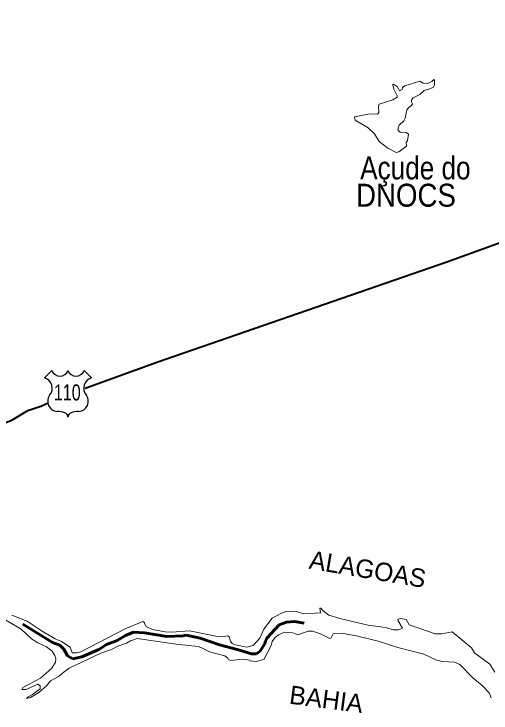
# Model space of a CAD drawing. Extents: x 553962 to 842807, y 8883888 to 9032388.
# Drawn here: x 591570 to 601949, y 8954910 to 8970115 of the extents above; entities that cross this region are included whole.
import ezdxf
from ezdxf.enums import TextEntityAlignment as Align

# ---------------------------------------------------------------- set-up
doc = ezdxf.new("R2010")
doc.units = 0
doc.header["$LTSCALE"] = 200
doc.linetypes.add('LONG_DASH_SHORT_DASH', pattern=[9.9, 6, -1.2, 1.5, -1.2])
for name, color, linetype, lineweight in [('12', 7, 'Continuous', 25), ('22', 7, 'Continuous', 13), ('25', 7, 'Continuous', 13), ('48', 7, 'Continuous', 25), ('7', 7, 'Continuous', 90), ('9', 7, 'Continuous', 90)]:
    doc.layers.add(name, color=color, linetype=linetype, lineweight=lineweight)
doc.layers.add('42', color=7, linetype='Continuous')
doc.layers.add('50', color=7, linetype='Continuous')

msp = doc.modelspace()

# ---------------------------------------------------------------- linework, layer by layer
at = {"layer": '12', "lineweight": 40}
for points in [[(593118.3, 8961975.5), (594700.8, 8962547.5), (600985.5, 8964722.4), (602091.6, 8965119.9), (602697.1, 8965318.9), (609861, 8967928.7)], [(587134, 8956453.8), (587843.6, 8957685.7), (587923.7, 8957988.5), (588169.9, 8958625.1), (588237, 8958904.7), (588304.1, 8959099.5), (588468, 8959448.9), (588578.9, 8959635.8), (588673.7, 8959750.1), (588777.5, 8959843.1), (589203.6, 8960089.7), (589393.4, 8960175.8), (589428.5, 8960178.5), (589560.1, 8960264.6), (589648.9, 8960297.2), (590059.4, 8960543.5), (591188.1, 8961101.4), (591408.7, 8961235.4), (591525.3, 8961280.9), (591868.7, 8961488.1), (592154.1, 8961587.2), (592311.1, 8961655)]]:
    msp.add_lwpolyline(points, dxfattribs=at)
at = {"layer": '22'}
for points in [[(599809.1, 8968571.9), (599807.2, 8968579.6), (599825.8, 8968589.3), (599913, 8968531.8), (599957.7, 8968446.1), (600016.8, 8968470.3), (600024, 8968513.4), (600074.7, 8968549.4), (600397.5, 8968653.6), (600470.2, 8968613.3), (600565, 8968605), (600658.8, 8968647.2), (600702.7, 8968690.5), (600704.6, 8968688.3)], [(600704.6, 8968688.3), (600721.8, 8968668.3), (600716.4, 8968577.4), (600697.2, 8968526.2), (600615.2, 8968484), (600495.5, 8968451.8), (600399.8, 8968360.6), (600257.6, 8968290.3), (600215.3, 8968243.9), (600215.2, 8968203.3), (600238.2, 8968158.5), (600215, 8968118.4), (600157.8, 8968080.1), (600117.6, 8968027.2), (600078.7, 8967845.6), (600049.3, 8967791.2), (599953.8, 8967693.5), (599926.3, 8967638.5), (599930.5, 8967583.1), (599969.1, 8967544.5), (600104.8, 8967540.5), (600151.1, 8967502.5), (600134.3, 8967366.4), (600104.7, 8967317.5), (600109.2, 8967237.7)], [(598979.7, 8967874.9), (598979.6, 8967875.5), (599301.7, 8967946.2), (599480.2, 8967933.8), (599509.8, 8967969.9), (599501.3, 8968101.1), (599516.3, 8968150.1), (599811.5, 8968247.9), (599904.8, 8968303.2), (599909, 8968337.3), (599832.8, 8968479.3), (599809.1, 8968571.9)], [(599516.6, 8967344.8), (599411.9, 8967506.8), (599276.3, 8967640.2), (598993.8, 8967806), (598979.7, 8967874.9)], [(600109.2, 8967237.7), (599943.1, 8967117.9), (599886.4, 8967105.1), (599701.2, 8967194.2), (599516.6, 8967344.8)]]:
    msp.add_lwpolyline(points, dxfattribs=at)
at = {"layer": '25'}
for points in [[(602034.6, 8955801.4), (601924, 8955971.4), (601588.5, 8956218.1), (601523.3, 8956327.4), (601101.6, 8956673.9), (600881.9, 8956635.9), (600732.9, 8956633.6), (600171.5, 8956830.7), (600105.7, 8956947.1), (599975.9, 8956965.8), (599923.2, 8956948.3), (599930.5, 8956912), (600022.6, 8956753.4), (599933.1, 8956722.5), (599825.2, 8956722.6), (599652.7, 8956767.8), (599276.6, 8956821.3), (598658.4, 8956963), (598417.2, 8957037), (598286.2, 8957141.3), (598243.2, 8957190.3), (598226.2, 8957190.3), (598238.1, 8957092.3), (597879.3, 8957064.6), (597707.1, 8957116.2), (597507.8, 8957122.3), (597374.1, 8957077.1), (597186.1, 8956972.4), (597004.9, 8956736.8), (596919, 8956537.3), (596774.8, 8956375.5), (596632.8, 8956343.6), (596391.2, 8956391.8), (596318.4, 8956424.7), (596280.9, 8956471.9), (596249.4, 8956564), (596220.4, 8956588.7), (596094.6, 8956570.7), (595996.6, 8956575.1), (595390.8, 8956696.7), (595007.1, 8956666.9), (594862.5, 8956673.6)], [(594862.5, 8956673.6), (594585.9, 8956725.5), (594444.6, 8956791.6), (594420.1, 8956840.6), (594411.5, 8956881.7), (594373.8, 8956897.2), (593986.5, 8956741.5), (593024.9, 8956242.6), (592929.9, 8956217.7), (592835, 8956222.8), (592789.7, 8956341.7), (592606.3, 8956465.9), (592465.6, 8956523.5), (592181.6, 8956687.1), (591853.4, 8956904.4), (591520.9, 8957037.4)], [(591390.8, 8956926.9), (591724.8, 8956737.2), (591949.4, 8956523.8), (592086.2, 8956435.1), (592274.8, 8956349.3), (592397.3, 8956258.1), (592456.5, 8956160.4), (592477.4, 8956090.3), (592474.5, 8956017), (592393.6, 8955882.5), (592147.6, 8955671.4), (591762.8, 8955464.9)], [(597003.9, 8956073.5), (597167.4, 8956377.6), (597189.2, 8956464.2), (597246.3, 8956548.8), (597323.6, 8956610.2), (597458.5, 8956666.4), (597633.6, 8956656.2), (597747.2, 8956610.1), (597972.1, 8956689.8), (598064.1, 8956689.8), (598239.7, 8956635), (598443.1, 8956534.1), (598468, 8956546.2), (598513.2, 8956629.3), (598729.6, 8956640.7), (599018.9, 8956591.1), (599495.2, 8956473.1), (599918.7, 8956332), (600484.8, 8956190.4), (600746.5, 8956064.1), (600895.5, 8956031), (601154.5, 8956013.6), (601268.1, 8955965.7), (601556.7, 8955677.2), (601755.9, 8955508), (601906.3, 8955346.6), (601953.1, 8955243.3)], [(591762.8, 8955464.9), (591742.8, 8955422.7), (591836, 8955420.5), (592092.2, 8955540.4), (592137.1, 8955502.8), (592137.1, 8955438.7), (591972.1, 8955314.2), (591880.4, 8955265.1), (591844.9, 8955225.2), (591926.5, 8955246.3), (592111.5, 8955357.7), (592276, 8955503.1), (592363.4, 8955610), (592552.2, 8955708.7), (592624, 8955780.3), (592767.9, 8955885), (593458.4, 8956208.9), (593688.8, 8956290), (593826.7, 8956367.4), (594014.5, 8956427.2), (594104.1, 8956482.6), (594251.8, 8956534.1), (595099, 8956405.8), (595575.6, 8956353.7), (595673.6, 8956322.5), (595827.2, 8956241.5), (596157.4, 8956151.4), (596224.2, 8956103.8), (596238.8, 8956075.3), (596285.2, 8956053), (596551.6, 8956080.4), (596701.6, 8956061.6), (596708.8, 8956044.6), (596839, 8956031.7), (597003.9, 8956073.5)]]:
    msp.add_lwpolyline(points, dxfattribs=at)
at = {"layer": '48'}
for p, q in [((592235.2, 8962198.4), (592395.1, 8962358.3)), ((593094.5, 8962358.3), (593254.4, 8962198.4))]:
    msp.add_line(p, q, dxfattribs=at)
for centre, radius, start, end in [((592570, 8962425.3), 187.2, 200.95927, 339.04073), ((592919.6, 8962425.3), 187.2, 200.95927, 339.04073), ((592173.1, 8961976.6), 230.3, 317.5721, 74.36886), ((593316.5, 8961976.6), 230.3, 105.62774, 222.4279), ((592526.6, 8961691.4), 224.7, 144.73733, 264.65778), ((592963, 8961691.4), 224.7, 275.34222, 35.26267), ((592504.7, 8960877.9), 589.7, 72.89371, 89.90057), ((592650.4, 8961351.3), 94.4, 357.69345, 72.92955), ((592839.2, 8961351.3), 94.4, 107.07045, 182.30655), ((592984.9, 8960877.9), 589.7, 90.09943, 107.10629)]:
    msp.add_arc(centre, radius, start, end, dxfattribs=at)
at = {"layer": '7', "linetype": 'LONG_DASH_SHORT_DASH', "lineweight": 60}
msp.add_lwpolyline([(591763.5, 8956844.7), (592411.2, 8956442.8), (592564.9, 8956388.5), (592651.2, 8956302.3), (592733.4, 8956151.1), (592848.3, 8956090.3), (593046.8, 8956129.1), (593418.6, 8956289.1), (593583.1, 8956399.4), (593816.8, 8956488.1), (593998.4, 8956596.2), (594173.5, 8956669.6), (594413, 8956654.5), (594897.5, 8956576.7), (595243.6, 8956587.5), (595312.5, 8956604.7), (595624.1, 8956539.8), (596038.9, 8956395.1), (596423.7, 8956293.5), (596735, 8956198.4), (596838.5, 8956200.5), (596916.4, 8956245.8), (597028.8, 8956414.3), (597044.2, 8956483.7), (597078.6, 8956544), (597342.3, 8956831.6), (597500, 8956885.7), (597673.4, 8956903.1), (597880.7, 8956866.4), (597885, 8956866.3)], dxfattribs=at)
at = {"layer": '9'}
msp.add_spline([(592698.5, 8977198.4), (599903.5, 8973292.7), (608459.2, 8968138.2), (612674.8, 8965332.6), (616842, 8962096.4), (620005, 8958671.2), (621134, 8957974.7), (621473.4, 8956805.3), (621586.2, 8956597.5)], degree=3, dxfattribs=at)

# ---------------------------------------------------------------- texts
at = {"layer": '42'}
for s, rotation, p in [('ALAGOAS', 350.452, (599232.2, 8957841.5)), ('BAHIA', 352.646, (598339.8, 8955012.7))]:
    msp.add_text(s, height=400, rotation=rotation, dxfattribs=at).set_placement(p, align=Align.CENTER)
at = {"layer": '48', "width": 0.75}
msp.add_text('110', height=350, dxfattribs=at).set_placement((592728.7, 8961708.4), align=Align.CENTER)
at = {"layer": '50'}
for s, width, p in [('Açude do', 0.85, (600302.7, 8966516.8)), ('DNOCS', 0.9, (600098, 8965922.9))]:
    msp.add_text(s, height=500, dxfattribs=dict(at, width=width)).set_placement(p, align=Align.CENTER)

doc.saveas('drawing.dxf')
